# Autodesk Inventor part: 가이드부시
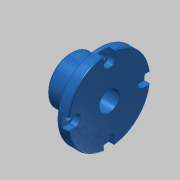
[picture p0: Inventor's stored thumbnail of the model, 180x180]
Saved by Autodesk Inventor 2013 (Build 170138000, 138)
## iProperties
Created: 2019-05
Part Number: 가이드부시
Material: 알루미늄 6061
Document SubType Name: Modeling
Designer: mduedu
Density: 2.71 g/cm^3
Mass: 81.3786 g
Surface Area: 96.2559 cm^2
Volume: 30.029 cm^3
Author: mduedu
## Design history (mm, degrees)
sketch "스케치1"
  geometry: C1 r 29 at (0, 0); 1 further point
  constraints: 1 centre point, 1 coincident
  dimensions: "d0" = 58 diameter of C1
extrude "돌출1" new body sketch "스케치1" distance "d1" = 7; taper "d2" = 0 deg
sketch "스케치2" dims "d3" = 48
  geometry: L1 (-4, 24)-(-4, 28.723); L2 (4, 24)-(4, 28.723); A1 r 4 centre (0, 24) between (-4, 24) and (4, 24); A2 r 29 centre (0, 0) between (-4, 28.723) and (4, 28.723) reference; A3 r 29 centre (0, 0) between (4, 28.723) and (-4, 28.723); 2 further points
  constraints: 6 point on circle, 4 end point, 2 centre point, 2 coincident, 2 tangent, 2 vertical alignment, 1 parallel, 1 vertical, 2 other
  dimensions: "d4" = 8 distance between parallel lines of L2 L1
extrude "돌출2" cut sketch "스케치2" distance "d5" = 4.4; taper "d6" = 0 deg
fillet "모깎기1" dims "d10" = 1
sketch "스케치3"
  geometry: C1 r 16.5 at (0, 0); 1 further point
  constraints: 1 centre point, 1 coincident
  dimensions: "d11" = 33 diameter of C1
extrude "돌출3" join sketch "스케치3" distance "d12" = 20; taper "d13" = 0 deg
sketch "스케치4"
  geometry: C1 r 7 at (0, 0); 1 further point
  constraints: 1 centre point, 1 coincident
  dimensions: "d14" = 14 diameter of C1
extrude "돌출4" cut sketch "스케치4" stored distance "d15" = 20; taper "d16" = 0 deg
chamfer "모따기1" distance "d17" = 1; stored, may be unused: second distance "d18" = 2, angle "d19" = 45 deg
chamfer "모따기2" distance "d20" = 1; stored, may be unused: second distance "d21" = 2, angle "d22" = 45 deg
sketch "스케치5" dims "d23" = 48
  geometry: 6 further points
  constraints: 2 vertical alignment, 1 coincident, 7 other
  dimensions: "d26" = 360 deg dimension on point (24, 0) point (24, 24) (derived)
sketch "스케치6"
  geometry: 4 further points
  constraints: 4 other
hole "구멍1" sketch "스케치6" at (-24, 24), (-48, 0), (-24, -24), (0, 0) diameter "d28" = 4.5; stored, may be unused: countersink angle "d32" = 90 deg, drill point angle "d34" = 0 deg; dims "d29" = 6, "d30" = 4, "d31" = 2, "d33" = 8
node "솔리드1"
pattern_circular "원형 패턴1" dims angle "d8" = 360 deg
